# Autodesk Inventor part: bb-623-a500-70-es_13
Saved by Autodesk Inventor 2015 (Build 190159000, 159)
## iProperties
Created: 2022-04
Part Number: bb-623-a500-70-es_13
Checked By: TraceParts S.A.
Material: Generic
Catalog Web Link: www.traceparts.com
Document SubType Name: Modeling
Designer: TraceParts
Density: 1 g/cm^3
Appearance: Default
Company: TraceParts S.A.
Author: TraceParts
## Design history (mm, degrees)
feature "bb-623-a500-70-es_13.ipt"
body "Solid1"
